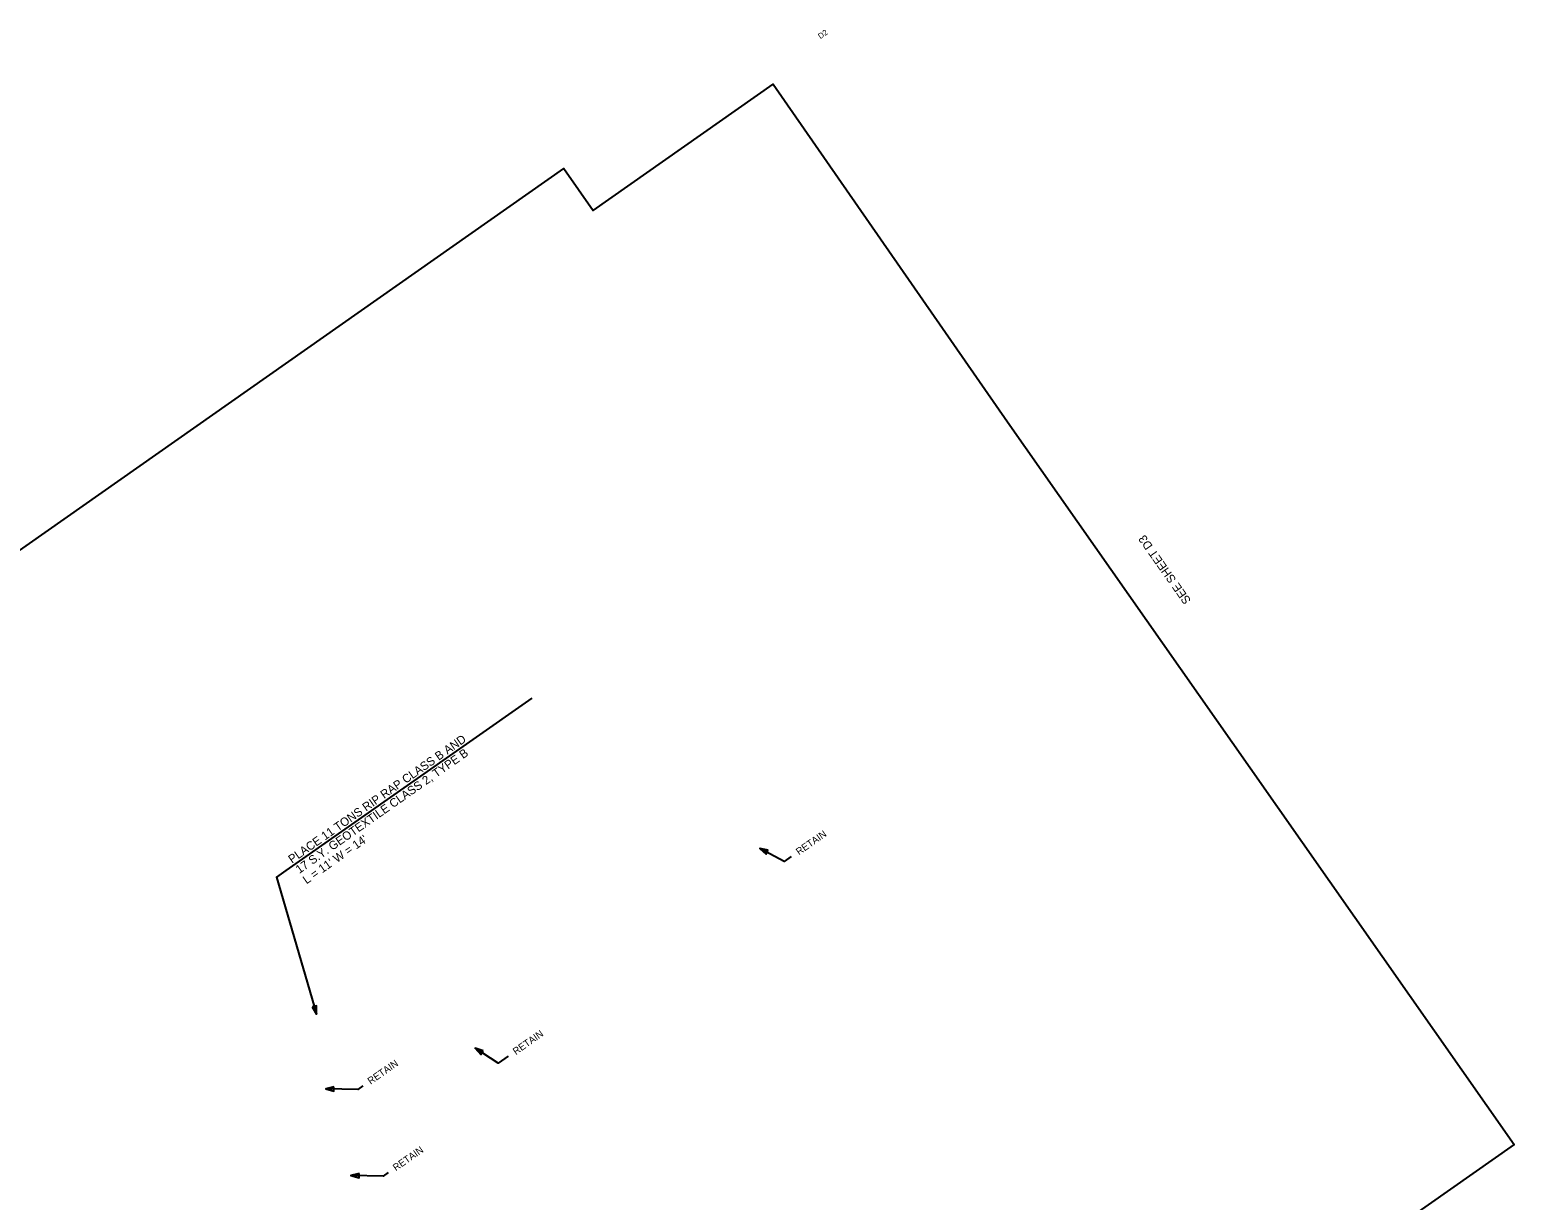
# Model space of a CAD drawing. Extents: x 1603736 to 1605697, y 1088463 to 1090389.
# Drawn here: x 1604540 to 1605593, y 1089559 to 1090389 of the extents above; entities that cross this region are included whole.
import ezdxf

# ---------------------------------------------------------------- set-up
doc = ezdxf.new("R2010")
doc.units = 0
for name, color, linetype in [('Plan_Clip', 7, 'Continuous'), ('RD_SHT_Bndy', 7, 'Continuous'), ('RD_SHT_MatchLine', 7, 'Continuous'), ('RD_TX_Drainage', 7, 'Continuous')]:
    doc.layers.add(name, color=color, linetype=linetype)

msp = doc.modelspace()

# ---------------------------------------------------------------- linework, layer by layer
at = {"layer": 'Plan_Clip'}
msp.add_lwpolyline([(1605233.6, 1090111), (1605405.8, 1089865.4), (1605593.1, 1089598.4), (1604362.4, 1088735.2), (1604177.8, 1089004.1), (1604005.5, 1089249.7), (1603817.5, 1089517.8), (1604919, 1090290.5), (1604939.8, 1090260.9), (1605067.4, 1090350.4)], close=True, dxfattribs=at)
msp.add_lwpolyline([(1605233.6, 1090111), (1605405.8, 1089865.4), (1605593.1, 1089598.4), (1604362.4, 1088735.2), (1604177.8, 1089004.1), (1604005.5, 1089249.7), (1603817.5, 1089517.8), (1604919, 1090290.5), (1604939.8, 1090260.9), (1605067.4, 1090350.4)], close=True, dxfattribs=at)
msp.add_lwpolyline([(1605233.6, 1090111), (1605405.8, 1089865.4), (1605593.1, 1089598.4), (1604362.4, 1088735.2), (1604177.8, 1089004.1), (1604005.5, 1089249.7), (1603817.5, 1089517.8), (1604919, 1090290.5), (1604939.8, 1090260.9), (1605067.4, 1090350.4)], close=True, dxfattribs=at)
msp.add_lwpolyline([(1605233.6, 1090111), (1605405.8, 1089865.4), (1605593.1, 1089598.4), (1604362.4, 1088735.2), (1604177.8, 1089004.1), (1604005.5, 1089249.7), (1603817.5, 1089517.8), (1604919, 1090290.5), (1604939.8, 1090260.9), (1605067.4, 1090350.4)], close=True, dxfattribs=at)
msp.add_lwpolyline([(1605233.6, 1090111), (1605405.8, 1089865.4), (1605593.1, 1089598.4), (1604362.4, 1088735.2), (1604177.8, 1089004.1), (1604005.5, 1089249.7), (1603817.5, 1089517.8), (1604919, 1090290.5), (1604939.8, 1090260.9), (1605067.4, 1090350.4)], close=True, dxfattribs=at)
msp.add_lwpolyline([(1605233.6, 1090111), (1605405.8, 1089865.4), (1605593.1, 1089598.4), (1604362.4, 1088735.2), (1604177.8, 1089004.1), (1604005.5, 1089249.7), (1603817.5, 1089517.8), (1604919, 1090290.5), (1604939.8, 1090260.9), (1605067.4, 1090350.4)], close=True, dxfattribs=at)
msp.add_lwpolyline([(1605233.6, 1090111), (1605405.8, 1089865.4), (1605593.1, 1089598.4), (1604362.4, 1088735.2), (1604177.8, 1089004.1), (1604005.5, 1089249.7), (1603817.5, 1089517.8), (1604919, 1090290.5), (1604939.8, 1090260.9), (1605067.4, 1090350.4)], close=True, dxfattribs=at)
msp.add_lwpolyline([(1605233.6, 1090111), (1605405.8, 1089865.4), (1605593.1, 1089598.4), (1604362.4, 1088735.2), (1604177.8, 1089004.1), (1604005.5, 1089249.7), (1603817.5, 1089517.8), (1604919, 1090290.5), (1604939.8, 1090260.9), (1605067.4, 1090350.4)], close=True, dxfattribs=at)
at = {"layer": 'RD_TX_Drainage'}
msp.add_line((1604896.3, 1089915), (1604721.8, 1089792.6), dxfattribs=at)
for points in [[(1605080.3, 1089802.6), (1605075.2, 1089799), (1605058.1, 1089808.4)], [(1604721.8, 1089792.6), (1604715.1, 1089788), (1604743.7, 1089690.8)], [(1604879.5, 1089660.9), (1604872.5, 1089656), (1604856.2, 1089666.7)], [(1604776.5, 1089639.9), (1604772.9, 1089637.4), (1604750.1, 1089637.8)], [(1604794.4, 1089578.4), (1604790.8, 1089575.9), (1604768, 1089576.4)]]:
    msp.add_lwpolyline(points, dxfattribs=at)
for points in [[(1605063.9, 1089807), (1605058.1, 1089808.4), (1605062.4, 1089804.3)], [(1604740.6, 1089695.9), (1604743.7, 1089690.8), (1604743.6, 1089696.8)], [(1604861.9, 1089664.8), (1604856.2, 1089666.7), (1604860.1, 1089662.2)], [(1604755.9, 1089639.3), (1604750.1, 1089637.8), (1604755.9, 1089636.2)], [(1604773.9, 1089577.8), (1604768, 1089576.4), (1604773.8, 1089574.7)]]:
    msp.add_lwpolyline(points, close=True, dxfattribs=at)

# ---------------------------------------------------------------- texts
at = {"layer": 'RD_SHT_Bndy'}
msp.add_text('D2', height=4, rotation=35.0468, dxfattribs=at).set_placement((1605101, 1090382.3))
at = {"layer": 'RD_SHT_MatchLine'}
msp.add_text('SEE SHEET D3', height=6, rotation=125.0981, dxfattribs=at).set_placement((1605364.1, 1089984.2))
at = {"layer": 'RD_TX_Drainage'}
for s, height, rotation, p in [('PLACE 11 TONS RIP RAP CLASS B AND', 6, 35.0468, (1604726.2, 1089797.5)), ('17 S.Y. GEOTEXTILE CLASS 2, TYPE B', 6, 35.0468, (1604731.4, 1089790.2)), ("L = 11' W = 14'", 6, 35.0468, (1604736.5, 1089782.8)), ('RETAIN', 5, 35.0468, (1605085.8, 1089803.4)), ('RETAIN', 5, 35.0902, (1604885, 1089661.7)), ('RETAIN', 5, 35.0468, (1604782, 1089640.7)), ('RETAIN', 5, 35.0468, (1604799.9, 1089579.3))]:
    msp.add_text(s, height=height, rotation=rotation, dxfattribs=at).set_placement(p)

doc.saveas('drawing.dxf')
